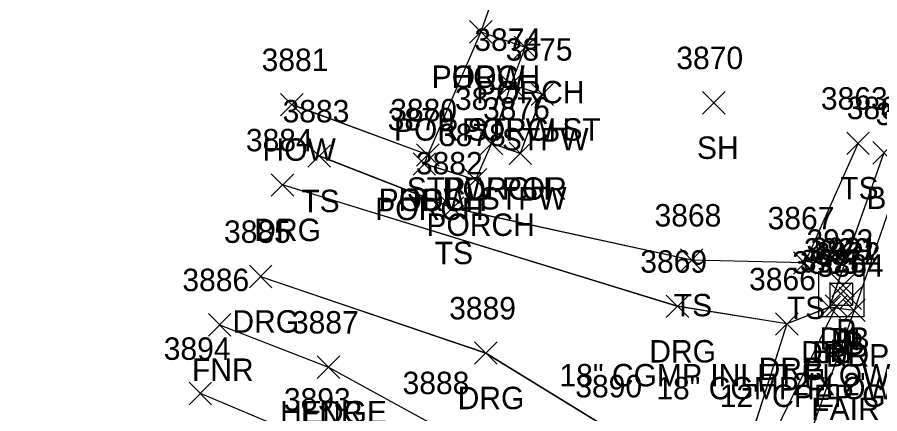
# Model space of a CAD drawing. Extents: x 1554668 to 1563881, y 831386 to 834374.
# Drawn here: x 1562460.9 to 1562537.7, y 834132.5 to 834167.8 of the extents above; entities that cross this region are included whole.
import ezdxf

# ---------------------------------------------------------------- set-up
doc = ezdxf.new("R2010")
doc.units = 0
for name, color, linetype in [('D_A', 7, 'Continuous'), ('D_C', 7, 'Continuous'), ('D_I', 7, 'Continuous'), ('D_TIC', 7, 'Continuous'), ('DCP', 7, 'Continuous'), ('DS', 7, 'Continuous'), ('L_A', 7, 'Continuous'), ('L_I', 7, 'Continuous'), ('L_TIC', 7, 'Continuous'), ('LAHR', 7, 'Continuous'), ('LBC', 7, 'Continuous'), ('LBF', 7, 'Continuous'), ('LELB', 7, 'Continuous'), ('LFNC', 7, 'Continuous'), ('P_A', 7, 'Continuous'), ('P_I', 7, 'Continuous'), ('P_TIC', 7, 'Continuous'), ('PET', 7, 'Continuous'), ('R_A', 7, 'Continuous'), ('R_I', 7, 'Continuous'), ('R_TIC', 7, 'Continuous'), ('RDG', 7, 'Continuous'), ('RDP', 7, 'Continuous')]:
    doc.layers.add(name, color=color, linetype=linetype)

msp = doc.modelspace()

# ---------------------------------------------------------------- linework, layer by layer
at = {"layer": 'D_TIC'}
for points in [[(1562533.48, 834142.889), (1562535.48, 834144.889)], [(1562535.48, 834142.889), (1562533.48, 834144.889)], [(1562533.283, 834142.154), (1562535.283, 834144.154)], [(1562535.283, 834142.154), (1562533.283, 834144.154)], [(1562534.118, 834141.741), (1562536.118, 834143.741)], [(1562536.118, 834141.741), (1562534.118, 834143.741)], [(1562532.892, 834141.054), (1562534.892, 834143.054)], [(1562534.892, 834141.054), (1562532.892, 834143.054)]]:
    msp.add_lwpolyline(points, dxfattribs=at)
at = {"layer": 'DCP'}
for points in [[(1562487.419, 834046.242), (1562533.892, 834142.054)], [(1562487.423, 834046.249), (1562533.895, 834142.059)], [(1562487.423, 834046.249), (1562533.895, 834142.059)], [(1562487.423, 834046.249), (1562533.895, 834142.059)]]:
    msp.add_lwpolyline(points, dxfattribs=at)
at = {"layer": 'DS'}
for p, q in [((1562532.328, 834145.094), (1562536.328, 834145.094)), ((1562532.328, 834141.094), (1562532.328, 834145.094)), ((1562536.328, 834145.094), (1562536.328, 834141.094)), ((1562533.328, 834142.094), (1562533.328, 834144.094)), ((1562533.328, 834144.094), (1562535.328, 834144.094)), ((1562535.328, 834144.094), (1562535.328, 834142.094)), ((1562534.333, 834143.096), (1562534.333, 834143.096)), ((1562534.333, 834143.096), (1562534.333, 834143.096)), ((1562535.328, 834142.094), (1562533.328, 834142.094)), ((1562536.328, 834141.094), (1562532.328, 834141.094))]:
    msp.add_line(p, q, dxfattribs=at)
at = {"layer": 'L_TIC'}
for points in [[(1562501.211, 834165.485), (1562503.211, 834167.485)], [(1562503.211, 834165.485), (1562501.211, 834167.485)], [(1562501.211, 834165.485), (1562503.211, 834167.485)], [(1562503.211, 834165.485), (1562501.211, 834167.485)], [(1562505.169, 834164.111), (1562507.169, 834166.111)], [(1562507.169, 834164.111), (1562505.169, 834166.111)], [(1562503.889, 834160.786), (1562505.889, 834162.786)], [(1562505.889, 834160.786), (1562503.889, 834162.786)], [(1562503.889, 834160.786), (1562505.889, 834162.786)], [(1562505.889, 834160.786), (1562503.889, 834162.786)], [(1562506.689, 834159.917), (1562508.689, 834161.917)], [(1562508.689, 834159.917), (1562506.689, 834161.917)], [(1562521.972, 834159.16), (1562523.972, 834161.16)], [(1562523.972, 834159.16), (1562521.972, 834161.16)], [(1562484.377, 834158.992), (1562486.377, 834160.992)], [(1562486.377, 834158.992), (1562484.377, 834160.992)], [(1562502.166, 834155.521), (1562504.166, 834157.521)], [(1562504.166, 834155.521), (1562502.166, 834157.521)], [(1562502.166, 834155.521), (1562504.166, 834157.521)], [(1562504.166, 834155.521), (1562502.166, 834157.521)], [(1562534.811, 834155.55), (1562536.811, 834157.55)], [(1562536.811, 834155.55), (1562534.811, 834157.55)], [(1562504.726, 834154.649), (1562506.726, 834156.649)], [(1562506.726, 834154.649), (1562504.726, 834156.649)], [(1562537.116, 834154.701), (1562539.116, 834156.701)], [(1562539.116, 834154.701), (1562537.116, 834156.701)], [(1562486.812, 834154.415), (1562488.812, 834156.415)], [(1562488.812, 834154.415), (1562486.812, 834156.415)], [(1562496.488, 834154.51), (1562498.488, 834156.51)], [(1562498.488, 834154.51), (1562496.488, 834156.51)], [(1562496.488, 834154.51), (1562498.488, 834156.51)], [(1562498.488, 834154.51), (1562496.488, 834156.51)], [(1562496.181, 834153.707), (1562498.181, 834155.707)], [(1562498.181, 834153.707), (1562496.181, 834155.707)], [(1562500.742, 834152.3), (1562502.742, 834154.3)], [(1562502.742, 834152.3), (1562500.742, 834154.3)], [(1562498.69, 834149.781), (1562500.69, 834151.781)], [(1562500.69, 834149.781), (1562498.69, 834151.781)], [(1562519.992, 834145.134), (1562521.992, 834147.134)], [(1562521.992, 834145.134), (1562519.992, 834147.134)], [(1562530.061, 834144.889), (1562532.061, 834146.889)], [(1562532.061, 834144.889), (1562530.061, 834146.889)], [(1562532.252, 834140.933), (1562534.252, 834142.933)], [(1562534.252, 834140.933), (1562532.252, 834142.933)], [(1562477.944, 834139.379), (1562479.944, 834141.379)], [(1562479.944, 834139.379), (1562477.944, 834141.379)], [(1562487.643, 834135.6), (1562489.643, 834137.6)], [(1562489.643, 834135.6), (1562487.643, 834137.6)], [(1562487.643, 834135.6), (1562489.643, 834137.6)], [(1562489.643, 834135.6), (1562487.643, 834137.6)]]:
    msp.add_lwpolyline(points, dxfattribs=at)
at = {"layer": 'LAHR'}
for points in [[(1562488.643, 834136.6), (1562498.502, 834131.198)], [(1562488.645, 834136.612), (1562498.505, 834131.209)], [(1562488.645, 834136.612), (1562498.505, 834131.209)], [(1562488.645, 834136.612), (1562498.505, 834131.209)]]:
    msp.add_lwpolyline(points, dxfattribs=at)
at = {"layer": 'LBC'}
for points in [[(1562506.74, 834179.399), (1562502.211, 834166.485), (1562497.488, 834155.51), (1562485.377, 834159.992)], [(1562506.744, 834179.411), (1562502.215, 834166.497), (1562497.492, 834155.515), (1562485.38, 834160.003)], [(1562506.744, 834179.411), (1562502.215, 834166.497), (1562497.492, 834155.515), (1562485.38, 834160.003)], [(1562506.744, 834179.411), (1562502.215, 834166.497), (1562497.492, 834155.515), (1562485.38, 834160.003)]]:
    msp.add_lwpolyline(points, dxfattribs=at)
at = {"layer": 'LBF'}
for points in [[(1562502.211, 834166.485), (1562506.169, 834165.111), (1562504.889, 834161.786), (1562503.166, 834156.521), (1562501.742, 834153.3), (1562497.181, 834154.707), (1562497.488, 834155.51)], [(1562502.215, 834166.497), (1562506.172, 834165.12), (1562504.893, 834161.792), (1562503.17, 834156.525), (1562501.747, 834153.305), (1562497.184, 834154.714), (1562497.492, 834155.515)], [(1562502.215, 834166.497), (1562506.172, 834165.12), (1562504.893, 834161.792), (1562503.17, 834156.525), (1562501.747, 834153.305), (1562497.184, 834154.714), (1562497.492, 834155.515)], [(1562502.215, 834166.497), (1562506.172, 834165.12), (1562504.893, 834161.792), (1562503.17, 834156.525), (1562501.747, 834153.305), (1562497.184, 834154.714), (1562497.492, 834155.515)], [(1562504.889, 834161.786), (1562507.689, 834160.917), (1562505.726, 834155.649), (1562503.166, 834156.521)], [(1562504.893, 834161.792), (1562507.692, 834160.928), (1562505.73, 834155.655), (1562503.17, 834156.525)], [(1562504.893, 834161.792), (1562507.692, 834160.928), (1562505.73, 834155.655), (1562503.17, 834156.525)], [(1562504.893, 834161.792), (1562507.692, 834160.928), (1562505.73, 834155.655), (1562503.17, 834156.525)]]:
    msp.add_lwpolyline(points, dxfattribs=at)
at = {"layer": 'LELB'}
for points in [[(1562535.811, 834156.55), (1562531.061, 834145.889), (1562520.992, 834146.134), (1562499.69, 834150.781), (1562487.812, 834155.415)], [(1562535.814, 834156.554), (1562531.065, 834145.897), (1562520.996, 834146.142), (1562499.694, 834150.787), (1562487.815, 834155.424)], [(1562535.814, 834156.554), (1562531.065, 834145.897), (1562520.996, 834146.142), (1562499.694, 834150.787), (1562487.815, 834155.424)], [(1562535.814, 834156.554), (1562531.065, 834145.897), (1562520.996, 834146.142), (1562499.694, 834150.787), (1562487.815, 834155.424)], [(1562538.116, 834155.701), (1562533.252, 834141.933)], [(1562538.119, 834155.714), (1562533.255, 834141.946)], [(1562538.119, 834155.714), (1562533.255, 834141.946)], [(1562538.119, 834155.714), (1562533.255, 834141.946)]]:
    msp.add_lwpolyline(points, dxfattribs=at)
at = {"layer": 'LFNC'}
for points in [[(1562478.944, 834140.379), (1562488.643, 834136.6)], [(1562478.947, 834140.39), (1562488.645, 834136.612)], [(1562478.947, 834140.39), (1562488.645, 834136.612)], [(1562478.947, 834140.39), (1562488.645, 834136.612)]]:
    msp.add_lwpolyline(points, dxfattribs=at)
at = {"layer": 'P_TIC'}
for points in [[(1562534.453, 834140.658), (1562536.453, 834142.658)], [(1562536.453, 834140.658), (1562534.453, 834142.658)]]:
    msp.add_lwpolyline(points, dxfattribs=at)
at = {"layer": 'PET'}
for points in [[(1562540.117, 834155.169), (1562535.453, 834141.658), (1562520.445, 834099.502), (1562517.255, 834088.953), (1562513.654, 834087.815), (1562498.465, 834079.308), (1562486.03, 834076.048), (1562467.873, 834078.421), (1562437.906, 834083.019)], [(1562540.12, 834155.182), (1562535.456, 834141.666), (1562520.449, 834099.511), (1562517.258, 834088.963), (1562513.658, 834087.824), (1562498.468, 834079.316), (1562486.034, 834076.055), (1562467.875, 834078.433), (1562437.913, 834083.023)], [(1562540.12, 834155.182), (1562535.456, 834141.666), (1562520.449, 834099.511), (1562517.258, 834088.963), (1562513.658, 834087.824), (1562498.468, 834079.316), (1562486.034, 834076.055), (1562467.875, 834078.433), (1562437.913, 834083.023)], [(1562540.12, 834155.182), (1562535.456, 834141.666), (1562520.449, 834099.511), (1562517.258, 834088.963), (1562513.658, 834087.824), (1562498.468, 834079.316), (1562486.034, 834076.055), (1562467.875, 834078.433), (1562437.913, 834083.023)]]:
    msp.add_lwpolyline(points, dxfattribs=at)
at = {"layer": 'R_TIC'}
for points in [[(1562483.544, 834151.836), (1562485.544, 834153.836)], [(1562485.544, 834151.836), (1562483.544, 834153.836)], [(1562481.595, 834143.678), (1562483.595, 834145.678)], [(1562483.595, 834143.678), (1562481.595, 834145.678)], [(1562518.731, 834141.018), (1562520.731, 834143.018)], [(1562520.731, 834141.018), (1562518.731, 834143.018)], [(1562532.252, 834140.933), (1562534.252, 834142.933)], [(1562534.252, 834140.933), (1562532.252, 834142.933)], [(1562534.453, 834140.658), (1562536.453, 834142.658)], [(1562536.453, 834140.658), (1562534.453, 834142.658)], [(1562528.47, 834139.453), (1562530.47, 834141.453)], [(1562530.47, 834139.453), (1562528.47, 834141.453)], [(1562528.47, 834139.453), (1562530.47, 834141.453)], [(1562530.47, 834139.453), (1562528.47, 834141.453)], [(1562501.66, 834136.859), (1562503.66, 834138.859)], [(1562503.66, 834136.859), (1562501.66, 834138.859)], [(1562476.227, 834133.254), (1562478.227, 834135.254)], [(1562478.227, 834133.254), (1562476.227, 834135.254)]]:
    msp.add_lwpolyline(points, dxfattribs=at)
at = {"layer": 'RDG'}
for points in [[(1562529.47, 834140.453), (1562519.731, 834142.018), (1562484.544, 834152.836)], [(1562529.474, 834140.459), (1562519.735, 834142.027), (1562484.548, 834152.848)], [(1562529.474, 834140.459), (1562519.735, 834142.027), (1562484.548, 834152.848)], [(1562529.474, 834140.459), (1562519.735, 834142.027), (1562484.548, 834152.848)], [(1562482.595, 834144.678), (1562502.66, 834137.859), (1562513.972, 834130.91), (1562512.898, 834123.886), (1562502.634, 834124.72), (1562487.93, 834129.734), (1562477.227, 834134.254)], [(1562482.6, 834144.682), (1562502.663, 834137.871), (1562513.976, 834130.919), (1562512.901, 834123.898), (1562502.638, 834124.725), (1562487.935, 834129.741), (1562477.231, 834134.261)], [(1562482.6, 834144.682), (1562502.663, 834137.871), (1562513.976, 834130.919), (1562512.901, 834123.898), (1562502.638, 834124.725), (1562487.935, 834129.741), (1562477.231, 834134.261)], [(1562482.6, 834144.682), (1562502.663, 834137.871), (1562513.976, 834130.919), (1562512.901, 834123.898), (1562502.638, 834124.725), (1562487.935, 834129.741), (1562477.231, 834134.261)]]:
    msp.add_lwpolyline(points, dxfattribs=at)
at = {"layer": 'RDP'}
for points in [[(1562535.453, 834141.658), (1562533.252, 834141.933), (1562529.47, 834140.453), (1562520.099, 834110.95), (1562519.159, 834099.702), (1562513.654, 834087.815)], [(1562535.456, 834141.666), (1562533.255, 834141.946), (1562529.474, 834140.459), (1562520.103, 834110.955), (1562519.163, 834099.712), (1562513.658, 834087.824)], [(1562535.456, 834141.666), (1562533.255, 834141.946), (1562529.474, 834140.459), (1562520.103, 834110.955), (1562519.163, 834099.712), (1562513.658, 834087.824)], [(1562535.456, 834141.666), (1562533.255, 834141.946), (1562529.474, 834140.459), (1562520.103, 834110.955), (1562519.163, 834099.712), (1562513.658, 834087.824)]]:
    msp.add_lwpolyline(points, dxfattribs=at)

# ---------------------------------------------------------------- texts
at = {"layer": 'D_A'}
for s, p in [('P', (1562533.858, 834138.889)), ('DIB', (1562532.385, 834138.154)), ('DI', (1562533.388, 834138.096)), ('P', (1562534.496, 834137.741)), ('P', (1562533.27, 834137.054))]:
    msp.add_text(s, height=2, dxfattribs=at).set_placement(p)
at = {"layer": 'D_C'}
for s, p in [('18" CGMP INLET FLOWS FROM THE', (1562509.22, 834134.889)), ("2'X 2'", (1562529.971, 834134.096)), ('18" CGMP FLOWS TO SE', (1562517.843, 834133.741)), ('12" CPEP GOOD', (1562523.49, 834133.054)), ('FAIR', (1562531.653, 834131.889))]:
    msp.add_text(s, height=2, dxfattribs=at).set_placement(p)
at = {"layer": 'D_I'}
for s, p in [('3923', (1562531.22, 834146.889)), ('3920', (1562530.987, 834146.096)), ('3921', (1562531.59, 834146.154)), ('3922', (1562531.859, 834145.741)), ('3925', (1562530.632, 834145.054))]:
    msp.add_text(s, height=2, dxfattribs=at).set_placement(p)
at = {"layer": 'L_A'}
for s, p in [('PORCH', (1562497.833, 834161.485)), ('HOW', (1562499.597, 834161.485)), ('PORCH', (1562501.791, 834160.111)), ('POR STPW ST', (1562494.472, 834156.786)), ('PORCH', (1562500.511, 834156.786)), ('STPW', (1562504.083, 834155.917)), ('HOW', (1562482.762, 834154.992)), ('SH', (1562521.46, 834155.16)), ('STPW POR', (1562495.615, 834151.521)), ('PORCH', (1562498.788, 834151.521)), ('TS', (1562534.22, 834151.55)), ('BS', (1562536.557, 834150.701)), ('TS', (1562486.221, 834150.415)), ('PORCH', (1562493.11, 834150.51)), ('HOW', (1562494.874, 834150.51)), ('STPW', (1562502.12, 834150.649)), ('PORCH', (1562492.803, 834149.707)), ('PORCH', (1562497.364, 834148.3)), ('TS', (1562498.099, 834145.781)), ('TS', (1562519.402, 834141.134)), ('TS', (1562529.471, 834140.889)), ('BS', (1562531.693, 834136.933)), ('FNR', (1562476.48, 834135.379)), ('HEDGE', (1562484.344, 834131.6)), ('FNR', (1562486.178, 834131.6))]:
    msp.add_text(s, height=2, dxfattribs=at).set_placement(p)
at = {"layer": 'L_I'}
for s, p in [('3874', (1562501.629, 834164.786)), ('3874', (1562501.629, 834164.786)), ('3875', (1562504.429, 834163.917)), ('3881', (1562482.684, 834162.992)), ('3870', (1562519.626, 834163.16)), ('3877', (1562499.906, 834159.521)), ('3877', (1562499.906, 834159.521)), ('3863', (1562532.503, 834159.55)), ('3883', (1562484.552, 834158.415)), ('3880', (1562494.141, 834158.51)), ('3880', (1562494.141, 834158.51)), ('3876', (1562502.411, 834158.649)), ('3862', (1562534.809, 834158.701)), ('3879', (1562493.913, 834157.707)), ('3878', (1562498.482, 834156.3)), ('3882', (1562496.43, 834153.781)), ('3868', (1562517.685, 834149.134)), ('3867', (1562527.754, 834148.889)), ('3865', (1562529.945, 834144.933)), ('3886', (1562475.629, 834143.379)), ('3887', (1562485.383, 834139.6)), ('3887', (1562485.383, 834139.6)), ('3888', (1562495.242, 834134.198)), ('3888', (1562495.242, 834134.198))]:
    msp.add_text(s, height=2, dxfattribs=at).set_placement(p)
at = {"layer": 'P_A'}
msp.add_text('RDP', height=2, dxfattribs=at).set_placement((1562532.941, 834136.658))
at = {"layer": 'P_I'}
for s, p in [('3861', (1562537.376, 834158.169)), ('3864', (1562532.146, 834144.658))]:
    msp.add_text(s, height=2, dxfattribs=at).set_placement(p)
at = {"layer": 'R_A'}
for s, p in [('DRG', (1562482.033, 834147.836)), ('DRG', (1562480.083, 834139.678)), ('DRG', (1562517.219, 834137.018)), ('DRP', (1562530.74, 834136.933)), ('DRP', (1562532.941, 834136.658)), ('DRG', (1562526.958, 834135.453)), ('DRP', (1562526.958, 834135.453)), ('DRG', (1562500.148, 834132.859))]:
    msp.add_text(s, height=2, dxfattribs=at).set_placement(p)
at = {"layer": 'R_I'}
for s, p in [('3884', (1562481.285, 834155.836)), ('3885', (1562479.335, 834147.678)), ('3869', (1562516.416, 834145.018)), ('3865', (1562529.945, 834144.933)), ('3864', (1562532.146, 834144.658)), ('3866', (1562526.108, 834143.453)), ('3866', (1562526.108, 834143.453)), ('3889', (1562499.392, 834140.859)), ('3894', (1562473.968, 834137.254)), ('3890', (1562510.626, 834133.91)), ('3893', (1562484.671, 834132.734))]:
    msp.add_text(s, height=2, dxfattribs=at).set_placement(p)

doc.saveas('drawing.dxf')
